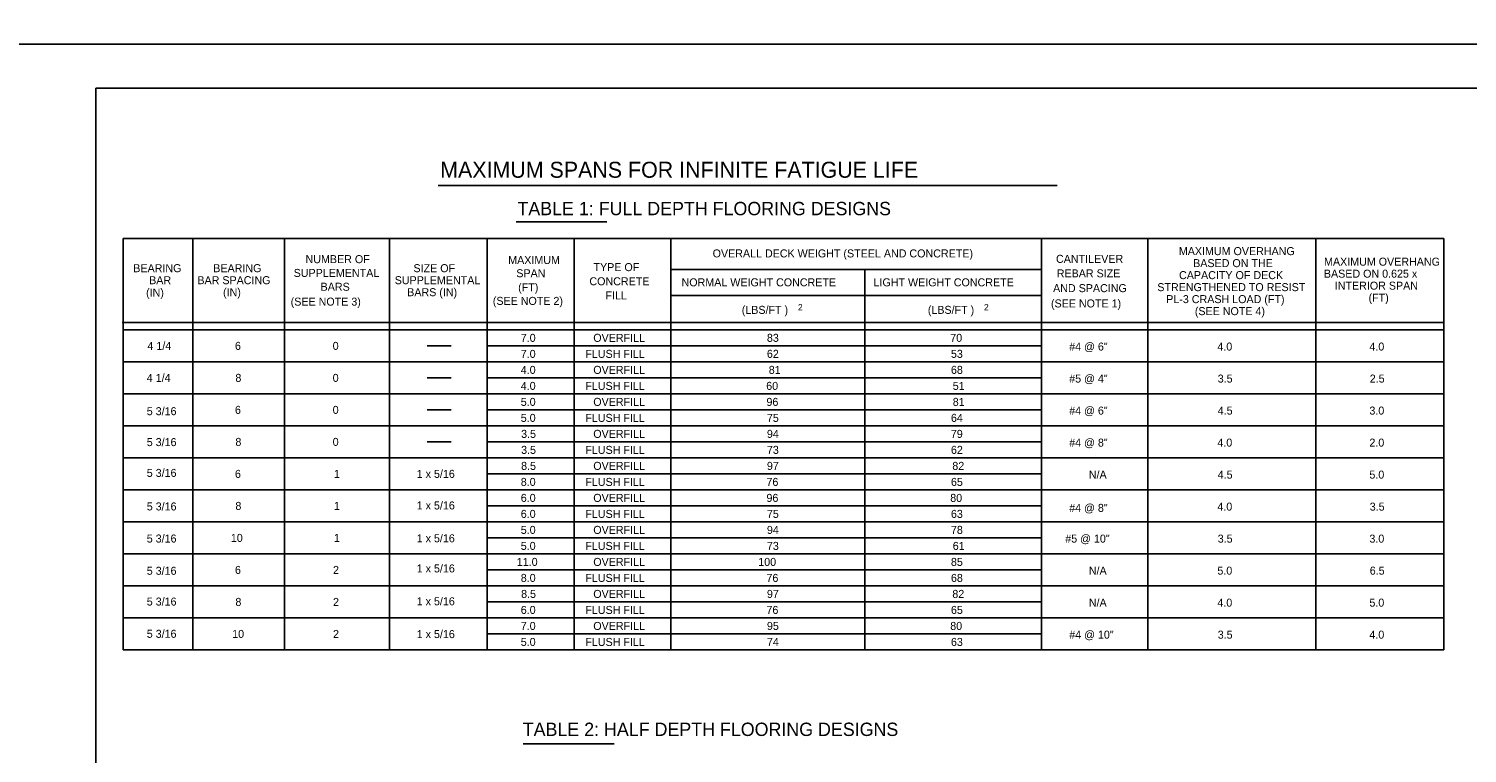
# Model space of a CAD drawing. Extents: x -24512 to -22484, y 4569 to 6351.
# Drawn here: x -23322 to -22783, y 5491 to 5763 of the extents above; entities that cross this region are included whole.
import ezdxf

# ---------------------------------------------------------------- set-up
doc = ezdxf.new("R2010")
doc.units = 0
for name, color, linetype in [('1', 7, 'Continuous'), ('2', 7, 'Continuous'), ('3', 7, 'Continuous'), ('6', 7, 'Continuous'), ('PLT-BNDY', 7, 'Continuous')]:
    doc.layers.add(name, color=color, linetype=linetype)

msp = doc.modelspace()

# ---------------------------------------------------------------- linework, layer by layer
at = {"layer": '2'}
for p, q in [((-23296.79, 5740.63), (-22512.75, 5740.63)), ((-23296.79, 5178.04), (-23296.79, 5740.63))]:
    msp.add_line(p, q, dxfattribs=at)
at = {"layer": '3'}
for p, q in [((-23286.53, 5529.97), (-23286.53, 5684.22)), ((-23286.53, 5684.22), (-22791.35, 5684.22)), ((-23260.41, 5529.97), (-23260.41, 5684.22)), ((-23226.09, 5529.97), (-23226.09, 5684.22)), ((-23186.66, 5529.97), (-23186.66, 5684.22)), ((-23150.09, 5529.97), (-23150.09, 5684.22)), ((-23117.51, 5529.97), (-23117.51, 5684.22)), ((-23081.19, 5529.97), (-23081.19, 5684.22)), ((-22942.27, 5529.97), (-22942.27, 5684.22)), ((-22902.35, 5529.97), (-22902.35, 5684.22)), ((-22839.35, 5529.97), (-22839.35, 5684.22)), ((-22791.35, 5529.97), (-22791.35, 5684.22)), ((-23081.19, 5672.62), (-22942.27, 5672.62)), ((-23008.44, 5529.97), (-23008.44, 5672.62)), ((-22942.27, 5662.81), (-23081.19, 5662.81)), ((-23286.88, 5652.77), (-22791.7, 5652.77)), ((-23286.53, 5649.96), (-22791.35, 5649.96)), ((-23150.09, 5643.96), (-22942.27, 5643.96)), ((-23286.53, 5637.97), (-23150.09, 5637.97)), ((-23150.03, 5637.97), (-22791.35, 5637.97)), ((-23150.09, 5631.97), (-22942.27, 5631.97)), ((-23286.53, 5625.96), (-23150.09, 5625.96)), ((-23150.03, 5625.96), (-22791.35, 5625.96)), ((-23150.09, 5619.96), (-22942.27, 5619.96)), ((-23286.53, 5613.96), (-23150.09, 5613.96)), ((-23150.03, 5613.96), (-22791.35, 5613.96)), ((-23150.09, 5607.97), (-22942.27, 5607.97)), ((-23286.53, 5601.97), (-23150.09, 5601.97)), ((-23150.03, 5601.97), (-22791.35, 5601.97)), ((-23150.09, 5595.97), (-22942.27, 5595.97)), ((-23286.53, 5589.97), (-23150.09, 5589.97)), ((-23150.03, 5589.97), (-22791.35, 5589.97)), ((-23150.09, 5583.96), (-22942.27, 5583.96)), ((-23286.53, 5577.97), (-23150.09, 5577.97)), ((-23150.03, 5577.97), (-22791.35, 5577.97)), ((-23150.09, 5571.97), (-22942.27, 5571.97)), ((-23286.53, 5565.97), (-23150.09, 5565.97)), ((-23150.03, 5565.97), (-22791.35, 5565.97)), ((-23150.09, 5559.97), (-22942.27, 5559.97)), ((-23286.53, 5553.97), (-23150.09, 5553.97)), ((-23150.03, 5553.97), (-22791.35, 5553.97)), ((-23150.09, 5547.97), (-22942.27, 5547.97)), ((-23286.53, 5541.97), (-23150.09, 5541.97)), ((-23150.03, 5541.97), (-22791.35, 5541.97)), ((-23150.09, 5535.97), (-22942.27, 5535.97)), ((-23286.53, 5529.97), (-22791.35, 5529.97))]:
    msp.add_line(p, q, dxfattribs=at)
at = {"layer": '6'}
for p, q in [((-23168.4, 5704.03), (-22936.34, 5704.03)), ((-23139.26, 5690.42), (-23105.21, 5690.42)), ((-23172.53, 5643.96), (-23163.53, 5643.96)), ((-23172.53, 5643.96), (-23163.53, 5643.96)), ((-23172.53, 5631.97), (-23163.53, 5631.97)), ((-23172.53, 5619.96), (-23163.53, 5619.96)), ((-23172.53, 5607.97), (-23163.53, 5607.97)), ((-23136.53, 5494.82), (-23102.49, 5494.82))]:
    msp.add_line(p, q, dxfattribs=at)
at = {"layer": 'PLT-BNDY'}
for points in [[(-23338.75, 6351.04), (-22497.75, 6351.04), (-22497.75, 5757.04), (-23338.75, 5757.04)], [(-23338.75, 5757.04), (-22497.75, 5757.04), (-22497.75, 5163.04), (-23338.75, 5163.04)]]:
    msp.add_lwpolyline(points, close=True, dxfattribs=at)

# ---------------------------------------------------------------- texts
at = {"layer": '1'}
for s, p in [('MAXIMUM OVERHANG', (-22890.74, 5677.98)), ('BASED ON THE', (-22885.37, 5673.48)), ('MAXIMUM OVERHANG', (-22836.3, 5674.03)), ('CAPACITY OF DECK', (-22890.66, 5668.98)), ('BASED ON 0.625 x', (-22836.36, 5669.53)), ('STRENGTHENED TO RESIST', (-22898.82, 5664.48)), ('PL-3 CRASH LOAD (FT)', (-22895.47, 5659.98)), ('INTERIOR SPAN', (-22832.28, 5665.03)), ('(FT)', (-22819.6, 5660.53)), ('(SEE NOTE 4)', (-22884.75, 5655.48)), ('4.0', (-22876.29, 5642.2)), ('4.0', (-22819.29, 5642.2)), ('3.5', (-22876.16, 5630.2)), ('2.5', (-22819.16, 5630.2)), ('4.5', (-22876.16, 5618.2)), ('3.0', (-22819.29, 5618.2)), ('4.0', (-22876.29, 5606.2)), ('2.0', (-22819.29, 5606.2)), ('4.5', (-22876.16, 5594.2)), ('5.0', (-22819.29, 5594.2)), ('4.0', (-22876.29, 5582.2)), ('3.5', (-22819.16, 5582.2)), ('3.5', (-22876.16, 5570.2)), ('3.0', (-22819.29, 5570.2)), ('5.0', (-22876.29, 5558.2)), ('6.5', (-22819.16, 5558.2)), ('4.0', (-22876.29, 5546.2)), ('5.0', (-22819.29, 5546.2)), ('3.5', (-22876.16, 5534.2)), ('4.0', (-22819.29, 5534.2))]:
    msp.add_text(s, height=3, dxfattribs=at).set_placement(p)
at = {"layer": '6'}
for s, height, p in [('MAXIMUM SPANS FOR INFINITE FATIGUE LIFE', 6, (-23167.7, 5706.98)), ('TABLE 1: FULL DEPTH FLOORING DESIGNS', 4.9998, (-23138.73, 5692.94)), ('OVERALL DECK WEIGHT (STEEL AND CONCRETE)', 2.9998, (-23065.54, 5677.12)), ('BEARING', 3, (-23282.77, 5671.58)), ('BEARING', 3, (-23252.78, 5671.58)), ('NUMBER OF', 3, (-23218.18, 5674.97)), ('SIZE OF', 3, (-23177.71, 5671.58)), ('MAXIMUM', 3, (-23142.19, 5674.64)), ('TYPE OF', 3, (-23110.21, 5671.98)), ('CANTILEVER', 3, (-22936.8, 5675.08)), ('BAR', 3, (-23276.82, 5667.08)), ('BAR SPACING', 2.9998, (-23258.73, 5667.08)), ('SUPPLEMENTAL', 2.9998, (-23222.63, 5669.81)), ('SUPPLEMENTAL', 2.9998, (-23184.74, 5667.08)), ('SPAN', 3, (-23139.16, 5669.69)), ('CONCRETE', 3, (-23111.75, 5666.67)), ('NORMAL WEIGHT CONCRETE', 2.9998, (-23077.2, 5666.28)), ('LIGHT WEIGHT CONCRETE', 2.9998, (-23005.21, 5666.28)), ('REBAR SIZE', 3, (-22936.51, 5669.64)), ('(IN)', 3, (-23277.97, 5662.44)), ('(IN)', 3, (-23249.11, 5662.58)), ('BARS', 3, (-23212.53, 5664.62)), ('BARS (IN)', 3, (-23180.06, 5662.58)), ('(FT)', 3, (-23138.46, 5664.42)), ('FILL', 3, (-23105.73, 5661.36)), ('AND SPACING', 3, (-22937.89, 5664.1)), ('(SEE NOTE 3)', 3, (-23223.75, 5659.05)), ('(SEE NOTE 2)', 3, (-23147.97, 5659.32)), ('(LBS/FT )', 3, (-23054.62, 5655.96)), ('2', 2.39, (-23033.56, 5657.24)), ('(LBS/FT )', 3, (-22984.86, 5655.96)), ('2', 2.39, (-22963.8, 5657.24)), ('(SEE NOTE 1)', 3, (-22938.68, 5658.37)), ('7.0', 3, (-23137.48, 5645.47)), ('OVERFILL', 3, (-23110.29, 5645.47)), ('83', 3, (-23045.19, 5645.47)), ('70', 3, (-22976.45, 5645.47)), ('4 1/4', 3, (-23277.46, 5642.46)), ('6', 3, (-23244.65, 5642.46)), ('0', 3, (-23208, 5642.46)), ('7.0', 3, (-23137.48, 5639.47)), ('FLUSH FILL', 3, (-23113.27, 5639.47)), ('62', 3, (-23045.19, 5639.47)), ('53', 3, (-22976.19, 5639.47)), ('#4 @ 6"', 3, (-22931.85, 5642.2)), ('4.0', 3, (-23137.48, 5633.46)), ('OVERFILL', 3, (-23110.29, 5633.46)), ('81', 3, (-23044.5, 5633.46)), ('68', 3, (-22976.19, 5633.46)), ('4 1/4', 3, (-23277.71, 5630.47)), ('8', 3, (-23244.48, 5630.47)), ('0', 3, (-23208, 5630.47)), ('#5 @ 4"', 3, (-22931.85, 5630.2)), ('4.0', 3, (-23137.48, 5627.46)), ('FLUSH FILL', 3, (-23113.27, 5627.46)), ('60', 3, (-23045.45, 5627.46)), ('51', 3, (-22975.51, 5627.46)), ('5 3/16', 3, (-23277.71, 5617.97)), ('6', 3, (-23244.65, 5618.47)), ('0', 3, (-23208, 5618.47)), ('5.0', 3, (-23137.48, 5621.46)), ('OVERFILL', 3, (-23110.29, 5621.46)), ('96', 3, (-23045.36, 5621.46)), ('81', 3, (-22975.51, 5621.46)), ('#4 @ 6"', 3, (-22931.85, 5618.2)), ('5.0', 3, (-23137.48, 5615.47)), ('FLUSH FILL', 3, (-23113.27, 5615.47)), ('75', 3, (-23045.19, 5615.47)), ('64', 3, (-22976.19, 5615.47)), ('5 3/16', 3, (-23277.71, 5606.38)), ('8', 3, (-23244.48, 5606.46)), ('0', 3, (-23208, 5606.46)), ('3.5', 3, (-23137.35, 5609.47)), ('OVERFILL', 3, (-23110.29, 5609.47)), ('94', 3, (-23045.19, 5609.47)), ('79', 3, (-22976.22, 5609.47)), ('#4 @ 8"', 3, (-22931.85, 5606.2)), ('3.5', 3, (-23137.35, 5603.47)), ('FLUSH FILL', 3, (-23113.27, 5603.47)), ('73', 3, (-23045.19, 5603.47)), ('62', 3, (-22976.19, 5603.47)), ('8.5', 3, (-23137.35, 5597.47)), ('OVERFILL', 3, (-23110.29, 5597.47)), ('97', 3, (-23045.19, 5597.47)), ('82', 3, (-22975.67, 5597.47)), ('5 3/16', 3, (-23277.71, 5594.84)), ('6', 3, (-23244.65, 5594.47)), ('1', 3, (-23207.53, 5594.47)), ('1 x 5/16', 3, (-23176.49, 5594.47)), ('8.0', 3, (-23137.48, 5591.46)), ('FLUSH FILL', 3, (-23113.27, 5591.46)), ('76', 3, (-23045.36, 5591.46)), ('65', 3, (-22976.19, 5591.46)), ('N/A', 3, (-22924.48, 5594.2)), ('6.0', 3, (-23137.48, 5585.47)), ('OVERFILL', 3, (-23110.29, 5585.47)), ('96', 3, (-23045.36, 5585.47)), ('80', 3, (-22976.45, 5585.47)), ('5 3/16', 3, (-23277.71, 5582.27)), ('8', 3, (-23244.48, 5582.47)), ('1', 3, (-23207.53, 5582.47)), ('1 x 5/16', 3, (-23176.49, 5582.64)), ('6.0', 3, (-23137.48, 5579.47)), ('FLUSH FILL', 3, (-23113.27, 5579.47)), ('75', 3, (-23045.19, 5579.47)), ('63', 3, (-22976.19, 5579.47)), ('#4 @ 8"', 3, (-22931.85, 5581.72)), ('5 3/16', 3, (-23277.71, 5570.23)), ('10', 3, (-23246.19, 5570.47)), ('1', 3, (-23207.53, 5570.47)), ('1 x 5/16', 3, (-23176.49, 5570.33)), ('5.0', 3, (-23137.48, 5573.47)), ('OVERFILL', 3, (-23110.29, 5573.47)), ('94', 3, (-23045.19, 5573.47)), ('78', 3, (-22976.19, 5573.47)), ('#5 @ 10"', 3, (-22933.33, 5570.2)), ('5.0', 3, (-23137.48, 5567.47)), ('FLUSH FILL', 3, (-23113.27, 5567.47)), ('73', 3, (-23045.19, 5567.47)), ('61', 3, (-22975.51, 5567.47)), ('5 3/16', 3, (-23277.71, 5558.15)), ('6', 3, (-23244.65, 5558.47)), ('2', 3, (-23207.87, 5558.47)), ('1 x 5/16', 3, (-23176.49, 5559.03)), ('11.0', 3, (-23138.97, 5561.47)), ('OVERFILL', 3, (-23110.29, 5561.47)), ('100', 3, (-23048.43, 5561.47)), ('85', 3, (-22976.19, 5561.47)), ('N/A', 3, (-22924.48, 5558.2)), ('8.0', 3, (-23137.48, 5555.47)), ('FLUSH FILL', 3, (-23113.27, 5555.47)), ('76', 3, (-23045.36, 5555.47)), ('68', 3, (-22976.19, 5555.47)), ('1 x 5/16', 3, (-23176.49, 5546.71)), ('8.5', 3, (-23137.35, 5549.47)), ('OVERFILL', 3, (-23110.29, 5549.47)), ('97', 3, (-23045.19, 5549.47)), ('82', 3, (-22975.67, 5549.47)), ('5 3/16', 3, (-23277.71, 5546.6)), ('8', 3, (-23244.48, 5546.47)), ('2', 3, (-23207.87, 5546.47)), ('6.0', 3, (-23137.48, 5543.47)), ('FLUSH FILL', 3, (-23113.27, 5543.47)), ('76', 3, (-23045.36, 5543.47)), ('65', 3, (-22976.19, 5543.47)), ('N/A', 3, (-22924.48, 5546.2)), ('7.0', 3, (-23137.48, 5537.47)), ('OVERFILL', 3, (-23110.29, 5537.47)), ('95', 3, (-23045.19, 5537.47)), ('80', 3, (-22976.45, 5537.47)), ('5 3/16', 3, (-23277.71, 5534.52)), ('10', 3, (-23245.69, 5534.47)), ('2', 3, (-23207.87, 5534.47)), ('1 x 5/16', 3, (-23176.49, 5534.41)), ('5.0', 3, (-23137.48, 5531.47)), ('FLUSH FILL', 3, (-23113.27, 5531.47)), ('74', 3, (-23045.19, 5531.47)), ('63', 3, (-22976.19, 5531.47)), ('#4 @ 10"', 3, (-22931.83, 5534.2)), ('TABLE 2: HALF DEPTH FLOORING DESIGNS', 5, (-23136.74, 5497.71))]:
    msp.add_text(s, height=height, dxfattribs=at).set_placement(p)

doc.saveas('drawing.dxf')
